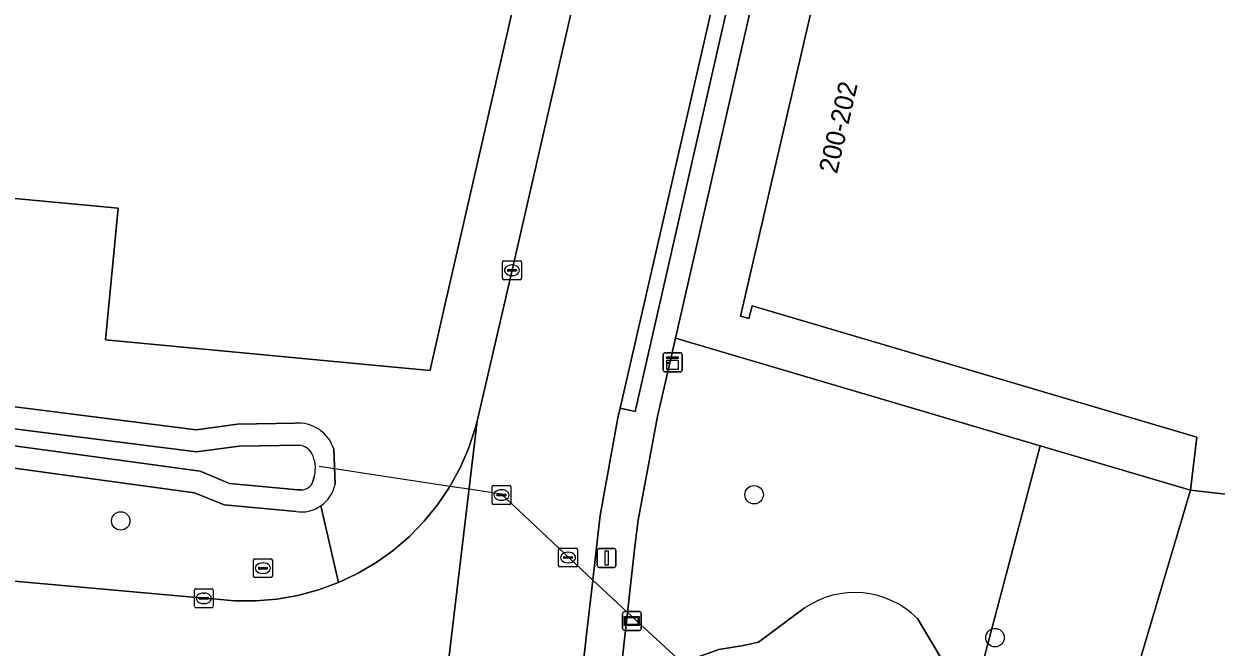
# Model space of a CAD drawing. Extents: x 161385 to 162589, y 388479 to 389756.
# Drawn here: x 162330.1 to 162393.2, y 388859.6 to 388892.6 of the extents above; entities that cross this region are included whole.
import ezdxf

# ---------------------------------------------------------------- set-up
doc = ezdxf.new("R2010")
doc.units = 0
for name, color, linetype in [('IMGEO_Berm_groen', 7, 'Continuous'), ('IMGEO_Boom', 7, 'Continuous'), ('IMGEO_Duiker', 7, 'Continuous'), ('IMGEO_Erf', 7, 'Continuous'), ('IMGEO_Groenvoorziening', 7, 'Continuous'), ('IMGEO_Kast', 7, 'Continuous'), ('IMGEO_Kolk', 7, 'Continuous'), ('IMGEO_Lichtmast', 7, 'Continuous'), ('IMGEO_Oever', 7, 'Continuous'), ('IMGEO_Pand', 7, 'Continuous'), ('IMGEO_Pand_nummerreeks', 7, 'Continuous'), ('IMGEO_Rijbaan_lokaal_gesloten', 7, 'Continuous'), ('IMGEO_Rioolput', 7, 'Continuous'), ('IMGEO_Verklikker', 7, 'Continuous'), ('IMGEO_Voetpad_open', 7, 'Continuous'), ('IMGEO_Waterloop', 7, 'Continuous')]:
    doc.layers.add(name, color=color, linetype=linetype)

msp = doc.modelspace()

# ---------------------------------------------------------------- linework, layer by layer
at = {"layer": 'IMGEO_Berm_groen'}
msp.add_lwpolyline([(162368.533, 388898.709), (162367.76, 388898.886), (162361.659, 388872.226), (162362.453, 388872.044)], close=True, dxfattribs=at)
at = {"layer": 'IMGEO_Boom'}
for centre in [(162368.753, 388867.635), (162335.225, 388866.247), (162381.503, 388860.065)]:
    msp.add_circle(centre, 0.489, dxfattribs=at)
at = {"layer": 'IMGEO_Duiker'}
msp.add_lwpolyline([(162365.584, 388858.13), (162365.112, 388858.568), (162362.048, 388861.405), (162360.956, 388862.417), (162360.209, 388863.109), (162355.382, 388867.663), (162353.656, 388867.925), (162352.651, 388868.077), (162346.541, 388869.005), (162345.729, 388869.128)], dxfattribs=at)
at = {"layer": 'IMGEO_Erf'}
msp.add_lwpolyline([(162369.717, 388898.438), (162364.588, 388875.934), (162383.901, 388870.224), (162391.857, 388867.872), (162392.177, 388870.683), (162368.656, 388877.64), (162368.47, 388876.966), (162368.037, 388877.085), (162373.582, 388901.101)], dxfattribs=at)
at = {"layer": 'IMGEO_Groenvoorziening'}
for points in [[(162345.812, 388867.043), (162346.747, 388862.984), (162347.764, 388863.464), (162348.735, 388864.034), (162349.65, 388864.688), (162350.503, 388865.422), (162351.288, 388866.228), (162351.997, 388867.101), (162352.625, 388868.035), (162352.651, 388868.077), (162353.186, 388869.057), (162353.631, 388870.082), (162353.982, 388871.142), (162354.085, 388871.528), (162355.936, 388879.524), (162364.598, 388917.339)], [(162357.822, 388901.413), (162352.295, 388877.281), (162351.615, 388874.313), (162351.606, 388874.213), (162348.394, 388874.517), (162334.421, 388875.837), (162335.09, 388882.809), (162329.062, 388883.383), (162328.267, 388875.021), (162322.959, 388875.526), (162322.786, 388873.71), (162322.717, 388872.815), (162324.614, 388872.923), (162339.222, 388871.074), (162341.408, 388871.373), (162344.443, 388871.418)], [(162383.901, 388870.224), (162364.588, 388875.934), (162363.642, 388871.781), (162362.617, 388866.281), (162362.437, 388864.885), (162362.048, 388861.405), (162356.744, 388813.903)], [(162344.503, 388866.742), (162340.703, 388867.092), (162339.127, 388867.743), (162324.286, 388869.767), (162324.463, 388871.47), (162324.614, 388872.923), (162322.717, 388872.815), (162322.632, 388871.715), (162322.016, 388863.733), (162325.24, 388863.441), (162339.626, 388862.148), (162340.13, 388862.129), (162341.25, 388862.022), (162342.375, 388862.016), (162343.496, 388862.11), (162344.605, 388862.304), (162345.691, 388862.596), (162346.747, 388862.984), (162345.812, 388867.043)], [(162346.502, 388870.058), (162346.571, 388868.186)], [(162377.396, 388861.07), (162380.214, 388856.331), (162383.901, 388870.224)], [(162364.379, 388857.968), (162365.642, 388859.002), (162366.878, 388859.435), (162368.182, 388859.647), (162368.992, 388859.83), (162371.408, 388861.618)]]:
    msp.add_lwpolyline(points, dxfattribs=at)
for points in [[(162391.857, 388867.872), (162383.901, 388870.224), (162380.214, 388856.331), (162368.059, 388811.153), (162367.935, 388809.448), (162367.141, 388807.636), (162366.551, 388805.446), (162368.834, 388805.186), (162368.553, 388803.357), (162372.558, 388802.943)], [(162383.532, 388830.458), (162383.919, 388830.342), (162392.007, 388856.692), (162398.712, 388854.634), (162401.565, 388863.931), (162427.905, 388860.918), (162428.16, 388863.668), (162427.372, 388863.825), (162391.857, 388867.872), (162372.558, 388802.943), (162376.55, 388802.484), (162377.177, 388802.419), (162377.914, 388804.888), (162375.474, 388805.196), (162374.122, 388805.367), (162382.047, 388830.873)]]:
    msp.add_lwpolyline(points, close=True, dxfattribs=at)
for centre, radius, start, end in [((162344.622, 388869.451), 1.975, 17.90517, 95.20413), ((162344.77, 388868.559), 1.839, 304.51688, 348.31146), ((162344.776, 388868.551), 1.83, 261.41415, 304.48555), ((162374.076, 388857.786), 4.67, 44.69406, 124.84807)]:
    msp.add_arc(centre, radius, start, end, dxfattribs=at)
at = {"layer": 'IMGEO_Kast'}
for p, q in [((162363.94, 388874.224), (162363.94, 388875.065)), ((162363.94, 388875.065), (162363.94, 388874.224)), ((162364.015, 388875.149), (162364.856, 388875.149)), ((162364.856, 388875.149), (162364.015, 388875.149)), ((162364.94, 388875.074), (162364.94, 388874.233)), ((162364.94, 388874.233), (162364.94, 388875.074)), ((162364.865, 388874.149), (162364.024, 388874.149)), ((162364.024, 388874.149), (162364.865, 388874.149))]:
    msp.add_line(p, q, dxfattribs=at)
for points in [[(162364.135, 388874.939), (162364.735, 388874.939), (162364.735, 388874.854), (162364.135, 388874.854), (162364.135, 388874.939)], [(162364.135, 388874.764), (162364.735, 388874.764), (162364.735, 388874.275), (162364.135, 388874.275), (162364.135, 388874.764)]]:
    msp.add_lwpolyline(points, dxfattribs=at)
msp.add_circle((162364.219, 388874.613), 0.0377, dxfattribs=at)
for centre, start, end in [((162364.018, 388875.071), 92.4484, 184.28452), ((162364.018, 388875.071), 92.4484, 184.28452), ((162364.862, 388875.071), 2.4484, 94.28452), ((162364.862, 388875.071), 2.4484, 94.28452), ((162364.018, 388874.227), 182.4484, 274.28452), ((162364.018, 388874.227), 182.4484, 274.28452), ((162364.862, 388874.227), 272.4484, 4.28452), ((162364.862, 388874.227), 272.4484, 4.28452)]:
    msp.add_arc(centre, 0.0779, start, end, dxfattribs=at)
at = {"layer": 'IMGEO_Kolk'}
for p, q in [((162355.509, 388880.024), (162356.361, 388880.024)), ((162355.434, 388879.098), (162355.434, 388879.95)), ((162355.693, 388879.518), (162355.693, 388879.53)), ((162356.131, 388879.481), (162355.733, 388879.481)), ((162355.736, 388879.567), (162356.134, 388879.567)), ((162355.922, 388879.804), (162355.947, 388879.804)), ((162356.177, 388879.53), (162356.177, 388879.518)), ((162356.435, 388879.95), (162356.435, 388879.098)), ((162356.361, 388879.024), (162355.509, 388879.024)), ((162355.945, 388879.244), (162355.92, 388879.244)), ((162339.124, 388861.723), (162339.124, 388862.575)), ((162339.199, 388862.649), (162340.051, 388862.649)), ((162339.612, 388862.429), (162339.637, 388862.429)), ((162340.125, 388862.575), (162340.125, 388861.723)), ((162339.383, 388862.143), (162339.383, 388862.155)), ((162339.821, 388862.106), (162339.423, 388862.106)), ((162339.426, 388862.192), (162339.824, 388862.192)), ((162339.635, 388861.869), (162339.61, 388861.869)), ((162339.867, 388862.155), (162339.867, 388862.143)), ((162340.051, 388861.649), (162339.199, 388861.649))]:
    msp.add_line(p, q, dxfattribs=at)
for points in [[(162355.509, 388880.024), (162356.361, 388880.024)], [(162355.434, 388879.098), (162355.434, 388879.95)], [(162356.435, 388879.95), (162356.435, 388879.098)], [(162356.361, 388879.024), (162355.509, 388879.024)], [(162339.124, 388861.723), (162339.124, 388862.575)], [(162339.199, 388862.649), (162340.051, 388862.649)], [(162340.125, 388862.575), (162340.125, 388861.723)], [(162340.051, 388861.649), (162339.199, 388861.649)]]:
    msp.add_lwpolyline(points, dxfattribs=at)
for centre, radius, start, end in [((162355.511, 388879.948), 0.0765, 91.55205, 178.44795), ((162355.511, 388879.948), 0.0765, 91.55205, 178.44795), ((162356.359, 388879.948), 0.0765, 1.55205, 88.44795), ((162356.359, 388879.948), 0.0765, 1.55205, 88.44795), ((162355.733, 388879.527), 0.0403, 85.87752, 175.75265), ((162355.73, 388879.517), 0.0366, 178.93798, 274.71019), ((162356.134, 388879.524), 0.043, 264.86636, 352.45326), ((162356.138, 388879.529), 0.0386, 1.73085, 96.63898), ((162355.511, 388879.1), 0.0765, 181.55205, 268.44795), ((162355.511, 388879.1), 0.0765, 181.55205, 268.44795), ((162356.359, 388879.1), 0.0765, 271.55205, 358.44795), ((162356.359, 388879.1), 0.0765, 271.55205, 358.44795), ((162339.201, 388862.573), 0.0765, 91.55205, 178.44795), ((162339.201, 388862.573), 0.0765, 91.55205, 178.44795), ((162340.049, 388862.573), 0.0765, 1.55205, 88.44795), ((162340.049, 388862.573), 0.0765, 1.55205, 88.44795), ((162339.201, 388861.725), 0.0765, 181.55205, 268.44795), ((162339.201, 388861.725), 0.0765, 181.55205, 268.44795), ((162339.423, 388862.152), 0.0403, 85.87752, 175.75265), ((162339.42, 388862.142), 0.0366, 178.93798, 274.71019), ((162339.824, 388862.149), 0.043, 264.86636, 352.45326), ((162339.828, 388862.154), 0.0386, 1.73085, 96.63898), ((162340.049, 388861.725), 0.0765, 271.55205, 358.44795), ((162340.049, 388861.725), 0.0765, 271.55205, 358.44795)]:
    msp.add_arc(centre, radius, start, end, dxfattribs=at)
for centre, major_axis, ratio, start_param, end_param in [((162355.921, 388879.524), (-0.387, 0.002), 0.722429, 4.712389, 7.853982), ((162355.946, 388879.524), (-0.39, 0.002), 0.717154, 1.570796, 4.712389), ((162339.611, 388862.149), (-0.387, 0.002), 0.722429, 4.712389, 7.853982), ((162339.636, 388862.149), (-0.39, 0.002), 0.717154, 1.570796, 4.712389)]:
    msp.add_ellipse(centre, major_axis=major_axis, ratio=ratio, start_param=start_param, end_param=end_param, dxfattribs=at)
at = {"layer": 'IMGEO_Lichtmast'}
for p, q in [((162360.449, 388863.885), (162360.449, 388864.685)), ((162360.449, 388864.685), (162360.449, 388863.885)), ((162360.549, 388864.785), (162361.339, 388864.785)), ((162361.339, 388864.785), (162360.549, 388864.785)), ((162361.439, 388864.685), (162361.439, 388863.885)), ((162361.439, 388863.885), (162361.439, 388864.685)), ((162361.339, 388863.785), (162360.549, 388863.785)), ((162360.549, 388863.785), (162361.339, 388863.785))]:
    msp.add_line(p, q, dxfattribs=at)
msp.add_lwpolyline([(162360.869, 388864.66), (162361.019, 388864.66), (162361.019, 388863.91), (162360.869, 388863.91), (162360.869, 388864.66)], dxfattribs=at)
for centre, start, end in [((162360.549, 388864.685), 90, 180), ((162360.549, 388864.685), 90, 180), ((162361.339, 388864.685), 0, 90), ((162361.339, 388864.685), 360, 90), ((162360.549, 388863.885), 180, 270), ((162360.549, 388863.885), 180, 270), ((162361.339, 388863.885), 270, 0), ((162361.339, 388863.885), 270, 0)]:
    msp.add_arc(centre, 0.1, start, end, dxfattribs=at)
at = {"layer": 'IMGEO_Oever'}
for points in [[(162344.443, 388871.418), (162341.408, 388871.373), (162339.222, 388871.074), (162324.614, 388872.923), (162324.463, 388871.47), (162324.286, 388869.767), (162339.127, 388867.743), (162340.703, 388867.092), (162344.503, 388866.742)], [(162325.561, 388870.768), (162325.389, 388870.843), (162325.243, 388870.943), (162325.175, 388871.03), (162325.117, 388871.285), (162325.192, 388871.512), (162325.275, 388871.574), (162325.447, 388871.614), (162325.649, 388871.618), (162339.228, 388869.9), (162341.496, 388870.21), (162344.685, 388870.255)], [(162344.776, 388867.889), (162344.6, 388867.902), (162340.985, 388868.235), (162339.433, 388868.876), (162325.561, 388870.768)], [(162346.571, 388868.186), (162346.502, 388870.058)], [(162345.479, 388868.637), (162345.401, 388868.329)], [(162371.408, 388861.618), (162368.992, 388859.83), (162368.182, 388859.647), (162366.878, 388859.435), (162365.642, 388859.002), (162364.379, 388857.968)], [(162380.214, 388856.331), (162377.396, 388861.07)]]:
    msp.add_lwpolyline(points, dxfattribs=at)
for centre, radius, start, end in [((162344.622, 388869.451), 1.975, 17.90517, 95.20413), ((162344.622, 388869.45), 0.807, 27.595, 85.55293), ((162343.822, 388869.042), 1.706, 346.26489, 27.2836), ((162344.774, 388868.555), 0.666, 270.142, 340.14909), ((162344.77, 388868.559), 1.839, 304.51688, 348.31146), ((162344.776, 388868.551), 1.83, 261.41415, 304.48555), ((162374.076, 388857.786), 4.67, 44.69406, 124.84807)]:
    msp.add_arc(centre, radius, start, end, dxfattribs=at)
at = {"layer": 'IMGEO_Pand'}
for points in [[(162329.062, 388883.383), (162335.09, 388882.809), (162334.421, 388875.837), (162348.394, 388874.517), (162351.606, 388874.213), (162351.615, 388874.313), (162352.295, 388877.281), (162357.822, 388901.413), (162350.993, 388902.975), (162351.799, 388906.466), (162359.012, 388937.762), (162358.244, 388937.938), (162354.138, 388938.878), (162348.019, 388940.254), (162347.32, 388937.213), (162321.535, 388943.142), (162322.217, 388946.171), (162311.401, 388948.624), (162301.281, 388884.015), (162300.445, 388878.969), (162300.833, 388878.935), (162311.923, 388877.971), (162312.587, 388884.951), (162316.198, 388884.607)], [(162391.857, 388867.872), (162427.372, 388863.825), (162430.252, 388889.19), (162396.969, 388892.972), (162380.807, 388897.743), (162381.135, 388898.887), (162380.7, 388899.012), (162380.594, 388898.564), (162373.932, 388900.514), (162374.02, 388900.974), (162373.582, 388901.101), (162368.037, 388877.085), (162368.47, 388876.966), (162368.656, 388877.64), (162392.177, 388870.683)]]:
    msp.add_lwpolyline(points, close=True, dxfattribs=at)
at = {"layer": 'IMGEO_Rijbaan_lokaal_gesloten'}
for points in [[(162364.598, 388917.339), (162355.936, 388879.524), (162354.085, 388871.528), (162350.544, 388841.795), (162349.892, 388835.959), (162348.515, 388823.765), (162348.397, 388822.686), (162347.549, 388814.966), (162346.508, 388805.67), (162345.796, 388799.312), (162345.085, 388792.96), (162344.038, 388783.802), (162351.507, 388784.973), (162351.586, 388785.803), (162354.609, 388813.12), (162354.707, 388814.075), (162359.887, 388860.235), (162360.209, 388863.109), (162360.509, 388865.779), (162360.606, 388866.537), (162361.541, 388871.709), (162361.659, 388872.226), (162367.76, 388898.886)], [(162350.544, 388841.795), (162354.085, 388871.528), (162353.982, 388871.142), (162353.631, 388870.082), (162353.186, 388869.057), (162352.651, 388868.077), (162352.625, 388868.035), (162351.997, 388867.101), (162351.288, 388866.228), (162350.503, 388865.422), (162349.65, 388864.688), (162348.735, 388864.034), (162347.764, 388863.464), (162346.747, 388862.984), (162345.691, 388862.596), (162344.605, 388862.304), (162343.496, 388862.11), (162342.375, 388862.016), (162341.25, 388862.022), (162340.13, 388862.129), (162339.626, 388862.148), (162325.24, 388863.441)]]:
    msp.add_lwpolyline(points, dxfattribs=at)
at = {"layer": 'IMGEO_Rioolput'}
for p, q in [((162354.878, 388867.194), (162354.878, 388868.046)), ((162354.953, 388868.12), (162355.805, 388868.12)), ((162355.879, 388868.046), (162355.879, 388867.194)), ((162355.137, 388867.614), (162355.137, 388867.626)), ((162355.575, 388867.577), (162355.177, 388867.577)), ((162355.18, 388867.663), (162355.578, 388867.663)), ((162355.389, 388867.34), (162355.364, 388867.34)), ((162355.366, 388867.9), (162355.391, 388867.9)), ((162355.621, 388867.626), (162355.621, 388867.614)), ((162355.805, 388867.12), (162354.953, 388867.12)), ((162342.325, 388864.242), (162343.177, 388864.242)), ((162358.4, 388863.883), (162358.4, 388864.735)), ((162358.475, 388864.809), (162359.327, 388864.809)), ((162358.659, 388864.303), (162358.659, 388864.315)), ((162359.097, 388864.266), (162358.699, 388864.266)), ((162358.702, 388864.352), (162359.1, 388864.352)), ((162358.888, 388864.589), (162358.913, 388864.589)), ((162359.143, 388864.315), (162359.143, 388864.303)), ((162359.401, 388864.735), (162359.401, 388863.883)), ((162342.25, 388863.316), (162342.25, 388864.168)), ((162342.509, 388863.736), (162342.509, 388863.748)), ((162342.947, 388863.699), (162342.549, 388863.699)), ((162342.552, 388863.785), (162342.95, 388863.785)), ((162342.738, 388864.022), (162342.763, 388864.022)), ((162342.993, 388863.748), (162342.993, 388863.736)), ((162343.251, 388864.168), (162343.251, 388863.316)), ((162359.327, 388863.809), (162358.475, 388863.809)), ((162358.911, 388864.029), (162358.886, 388864.029)), ((162343.177, 388863.242), (162342.325, 388863.242)), ((162342.761, 388863.462), (162342.736, 388863.462))]:
    msp.add_line(p, q, dxfattribs=at)
for points in [[(162354.878, 388867.194), (162354.878, 388868.046)], [(162354.953, 388868.12), (162355.805, 388868.12)], [(162355.879, 388868.046), (162355.879, 388867.194)], [(162355.805, 388867.12), (162354.953, 388867.12)], [(162342.325, 388864.242), (162343.177, 388864.242)], [(162358.4, 388863.883), (162358.4, 388864.735)], [(162358.475, 388864.809), (162359.327, 388864.809)], [(162359.401, 388864.735), (162359.401, 388863.883)], [(162342.25, 388863.316), (162342.25, 388864.168)], [(162343.251, 388864.168), (162343.251, 388863.316)], [(162359.327, 388863.809), (162358.475, 388863.809)], [(162343.177, 388863.242), (162342.325, 388863.242)]]:
    msp.add_lwpolyline(points, dxfattribs=at)
for centre, radius, start, end in [((162354.955, 388868.044), 0.0765, 91.55205, 178.44795), ((162354.955, 388868.044), 0.0765, 91.55205, 178.44795), ((162355.803, 388868.044), 0.0765, 1.55205, 88.44795), ((162355.803, 388868.044), 0.0765, 1.55205, 88.44795), ((162355.177, 388867.623), 0.0403, 85.87752, 175.75265), ((162355.174, 388867.613), 0.0366, 178.93798, 274.71019), ((162355.578, 388867.62), 0.043, 264.86636, 352.45326), ((162355.582, 388867.625), 0.0386, 1.73085, 96.63898), ((162354.955, 388867.196), 0.0765, 181.55205, 268.44795), ((162354.955, 388867.196), 0.0765, 181.55205, 268.44795), ((162355.803, 388867.196), 0.0765, 271.55205, 358.44795), ((162355.803, 388867.196), 0.0765, 271.55205, 358.44795), ((162342.327, 388864.166), 0.0765, 91.55205, 178.44795), ((162342.327, 388864.166), 0.0765, 91.55205, 178.44795), ((162343.175, 388864.166), 0.0765, 1.55205, 88.44795), ((162343.175, 388864.166), 0.0765, 1.55205, 88.44795), ((162358.477, 388864.733), 0.0765, 91.55205, 178.44795), ((162358.477, 388864.733), 0.0765, 91.55205, 178.44795), ((162358.699, 388864.312), 0.0403, 85.87752, 175.75265), ((162358.696, 388864.302), 0.0366, 178.93798, 274.71019), ((162359.1, 388864.309), 0.043, 264.86636, 352.45326), ((162359.104, 388864.314), 0.0386, 1.73085, 96.63898), ((162359.325, 388864.733), 0.0765, 1.55205, 88.44795), ((162359.325, 388864.733), 0.0765, 1.55205, 88.44795), ((162342.549, 388863.745), 0.0403, 85.87752, 175.75265), ((162342.546, 388863.735), 0.0366, 178.93798, 274.71019), ((162342.95, 388863.742), 0.043, 264.86636, 352.45326), ((162342.954, 388863.747), 0.0386, 1.73085, 96.63898), ((162358.477, 388863.885), 0.0765, 181.55205, 268.44795), ((162358.477, 388863.885), 0.0765, 181.55205, 268.44795), ((162359.325, 388863.885), 0.0765, 271.55205, 358.44795), ((162359.325, 388863.885), 0.0765, 271.55205, 358.44795), ((162342.327, 388863.318), 0.0765, 181.55205, 268.44795), ((162342.327, 388863.318), 0.0765, 181.55205, 268.44795), ((162343.175, 388863.318), 0.0765, 271.55205, 358.44795), ((162343.175, 388863.318), 0.0765, 271.55205, 358.44795)]:
    msp.add_arc(centre, radius, start, end, dxfattribs=at)
for centre, major_axis, ratio, start_param, end_param in [((162355.365, 388867.62), (-0.387, 0.002), 0.722429, 4.712389, 7.853982), ((162355.39, 388867.62), (-0.39, 0.002), 0.717154, 1.570796, 4.712389), ((162358.887, 388864.309), (-0.387, 0.002), 0.722429, 4.712389, 7.853982), ((162358.912, 388864.309), (-0.39, 0.002), 0.717154, 1.570796, 4.712389), ((162342.737, 388863.742), (-0.387, 0.002), 0.722429, 4.712389, 7.853982), ((162342.762, 388863.742), (-0.39, 0.002), 0.717154, 1.570796, 4.712389)]:
    msp.add_ellipse(centre, major_axis=major_axis, ratio=ratio, start_param=start_param, end_param=end_param, dxfattribs=at)
at = {"layer": 'IMGEO_Verklikker'}
for p, q in [((162361.786, 388860.547), (162361.786, 388861.347)), ((162361.786, 388861.347), (162361.786, 388860.547)), ((162361.886, 388861.447), (162362.676, 388861.447)), ((162362.676, 388861.447), (162361.886, 388861.447)), ((162362.776, 388861.347), (162362.776, 388860.547)), ((162362.776, 388860.547), (162362.776, 388861.347)), ((162362.676, 388860.447), (162361.886, 388860.447)), ((162361.886, 388860.447), (162362.676, 388860.447))]:
    msp.add_line(p, q, dxfattribs=at)
for points in [[(162361.887, 388861.179), (162362.675, 388861.179), (162362.675, 388860.715), (162361.887, 388860.715), (162361.887, 388861.179)], [(162361.952, 388861.114), (162361.952, 388860.78), (162362.61, 388860.78), (162362.61, 388861.114), (162361.952, 388861.114)]]:
    msp.add_lwpolyline(points, dxfattribs=at)
for centre, start, end in [((162361.886, 388861.347), 90, 180), ((162361.886, 388861.347), 90, 180), ((162362.676, 388861.347), 0, 90), ((162362.676, 388861.347), 360, 90), ((162361.886, 388860.547), 180, 270), ((162361.886, 388860.547), 180, 270), ((162362.676, 388860.547), 270, 0), ((162362.676, 388860.547), 270, 0)]:
    msp.add_arc(centre, 0.1, start, end, dxfattribs=at)
at = {"layer": 'IMGEO_Voetpad_open'}
msp.add_lwpolyline([(162362.048, 388861.405), (162362.437, 388864.885), (162362.617, 388866.281), (162363.642, 388871.781), (162364.588, 388875.934), (162369.717, 388898.438), (162368.533, 388898.709), (162362.453, 388872.044), (162361.659, 388872.226), (162361.541, 388871.709), (162360.606, 388866.537), (162360.509, 388865.779), (162360.209, 388863.109), (162359.887, 388860.235), (162354.707, 388814.075), (162356.744, 388813.903)], close=True, dxfattribs=at)
at = {"layer": 'IMGEO_Waterloop'}
for points in [[(162325.649, 388871.618), (162325.447, 388871.614), (162325.275, 388871.574), (162325.192, 388871.512), (162325.117, 388871.285), (162325.175, 388871.03), (162325.243, 388870.943), (162325.389, 388870.843), (162325.561, 388870.768), (162339.433, 388868.876), (162340.985, 388868.235), (162344.6, 388867.902), (162344.776, 388867.889)], [(162344.685, 388870.255), (162341.496, 388870.21), (162339.228, 388869.9), (162325.649, 388871.618)], [(162345.401, 388868.329), (162345.479, 388868.637)]]:
    msp.add_lwpolyline(points, dxfattribs=at)
for centre, radius, start, end in [((162344.622, 388869.45), 0.807, 27.595, 85.55293), ((162343.822, 388869.042), 1.706, 346.26489, 27.2836), ((162344.774, 388868.555), 0.666, 270.142, 340.14909)]:
    msp.add_arc(centre, radius, start, end, dxfattribs=at)

# ---------------------------------------------------------------- texts
at = {"layer": 'IMGEO_Pand_nummerreeks'}
msp.add_text('200-202', height=1, rotation=76.99894, dxfattribs=at).set_placement((162373.138, 388884.598))

doc.saveas('drawing.dxf')
